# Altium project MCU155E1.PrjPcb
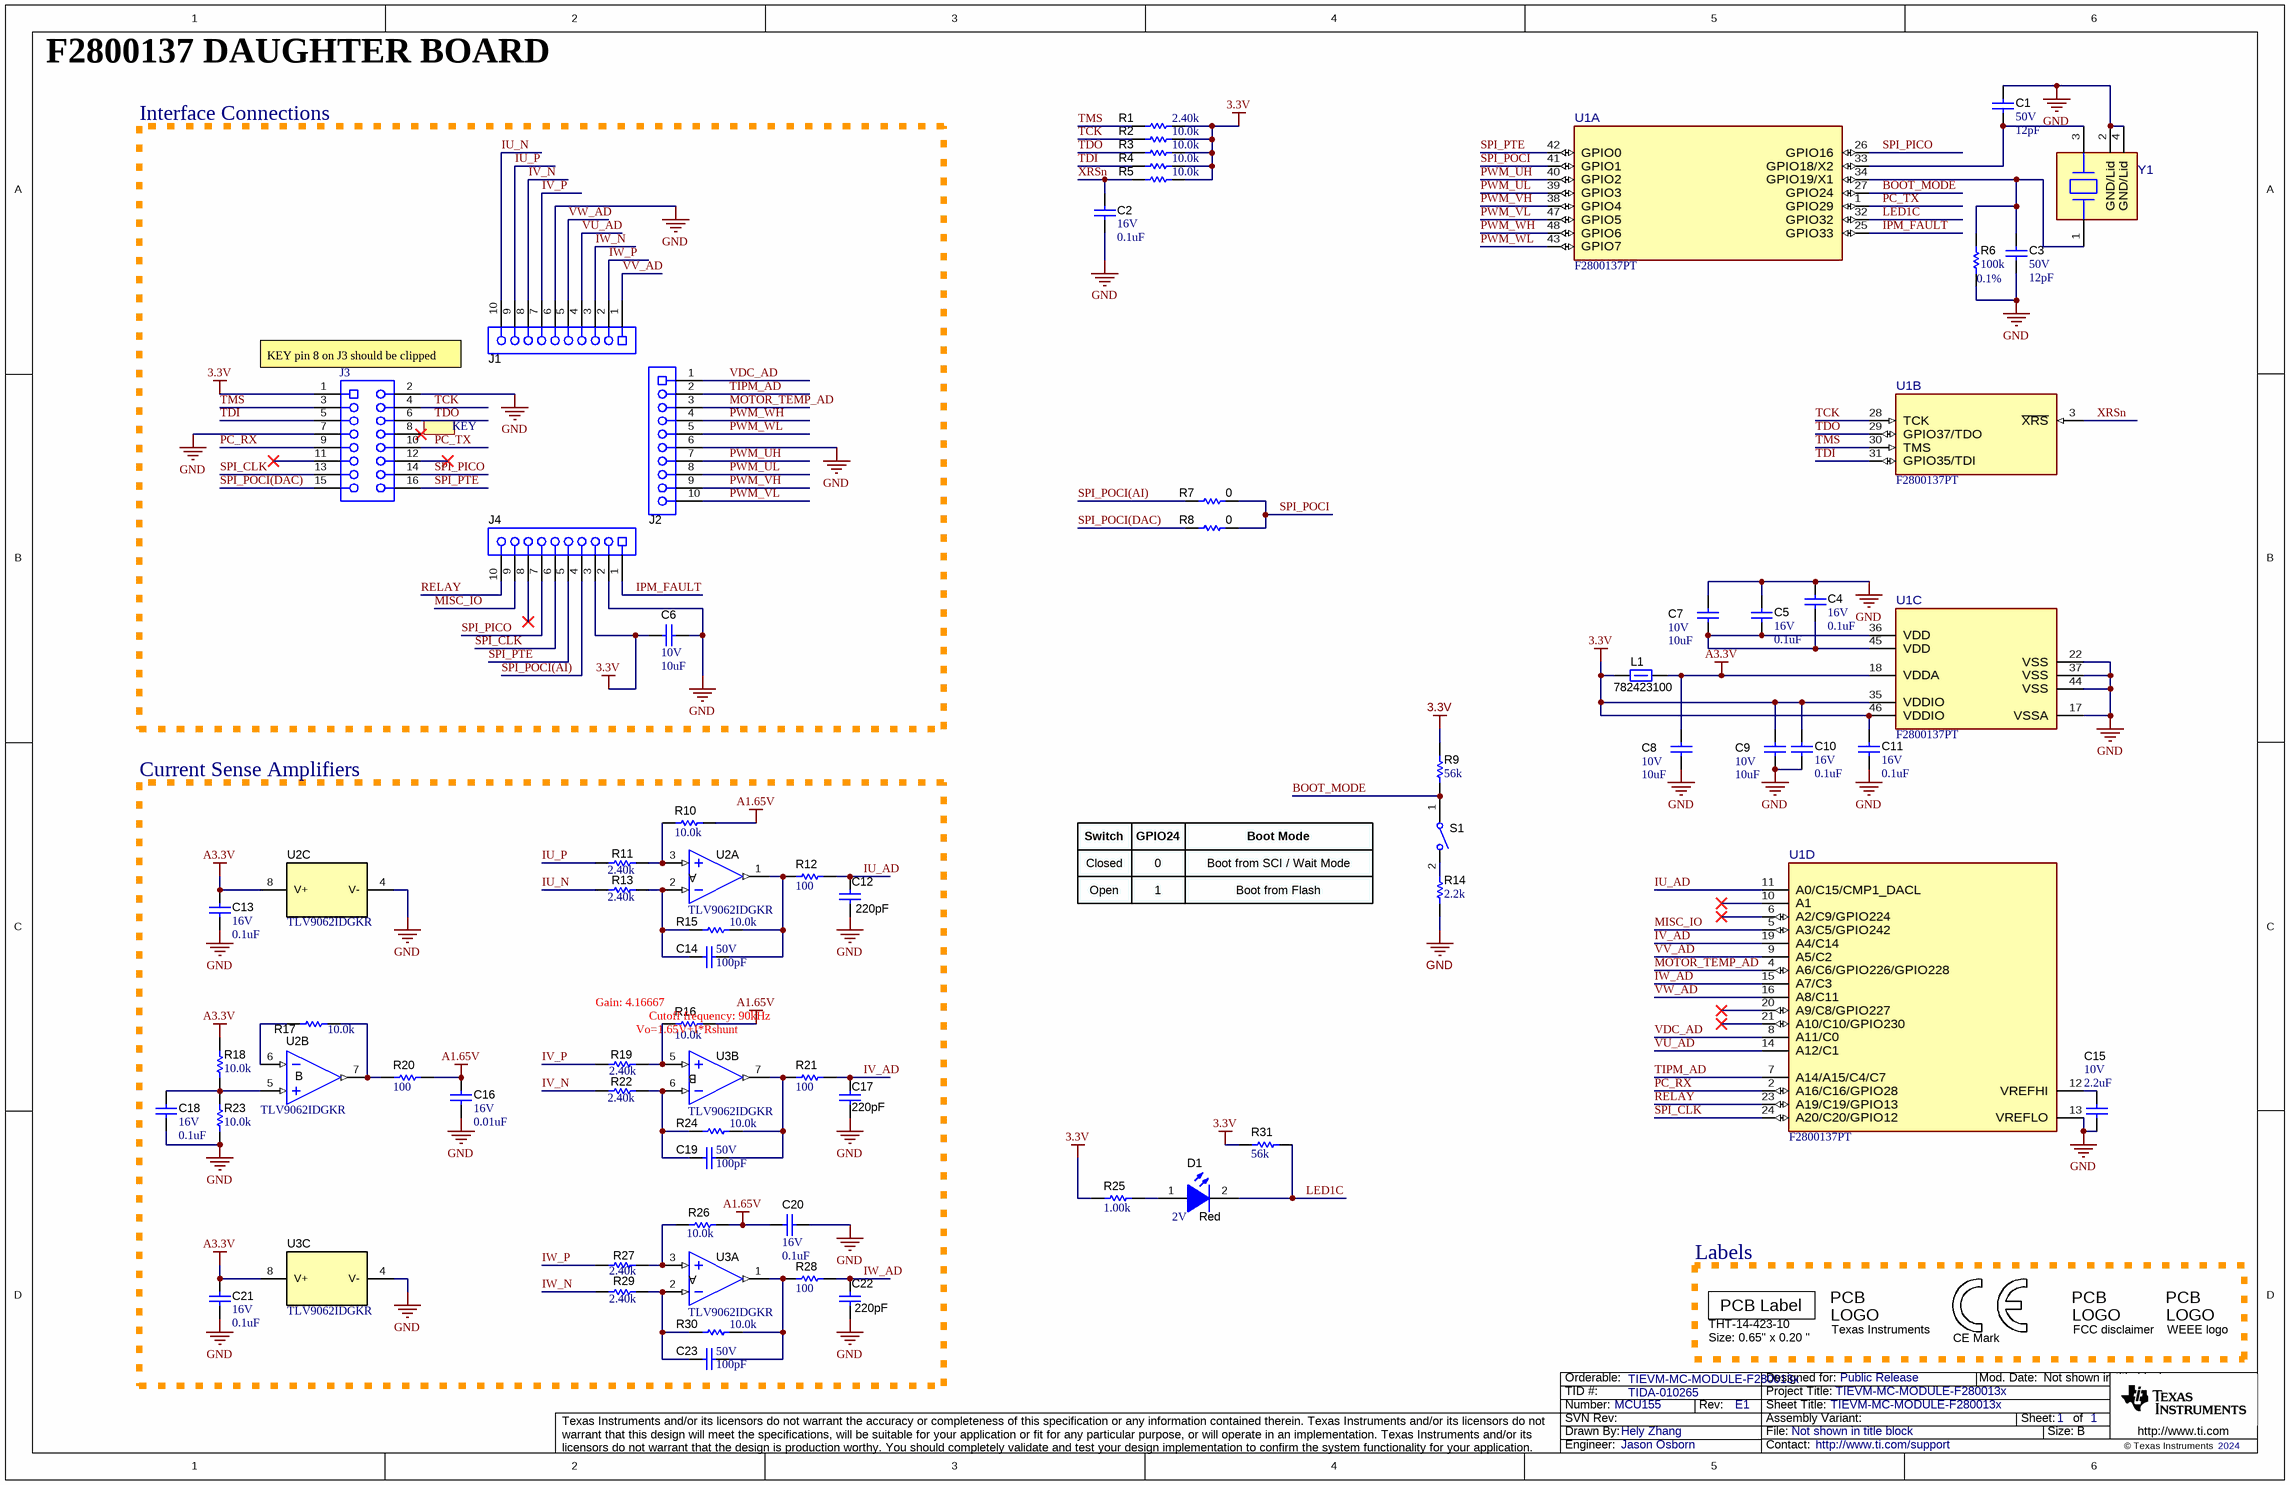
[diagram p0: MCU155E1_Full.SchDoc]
CopyrightYear: 2024; EVM_orderable: TIEVM-MC-MODULE-F280013x; PCB_Rev: E1; PRJ_Customer: Public Release; PRJ_Engineer: Jason Osborn; PRJ_Number: MCU155; PRJ_Title: TIEVM-MC-MODULE-F280013x; PRJ_Title_Short: TI-MC-M-F280013x; SCH_Rev: E1; TechSupport: http://www.ti.com/support; TID: TIDA-010265
1 sheet, 70 parts. Net scope: global (net labels, ports and power ports of the same name join across sheets).
Board file: MCU155E1_PCB.PcbDoc

## Sheet MCU155E1_Full.SchDoc: TIEVM-MC-MODULE-F280013x
size 431 x 279 mm; Date: Not shown in title block; ApprovedBy: Not shown in title block; CheckedBy: Not shown in title block; Author: Not shown in title block; CompanyName: Not shown in title block; DrawnBy: Hely Zhang; Engineer: Not shown in title block; Organization: Not shown in title block; Address1: Not shown in title block; Address2: Not shown in title block; Address3: Not shown in title block; Address4: Not shown in title block; DocumentNumber: 1; Revision: Use project parameter SCH_Rev; SheetNumber: 1; SheetTotal: 1; PageSetup: Record=PageOptions¦CenterHorizontal=True¦CenterVertical=True¦PrintScale=0.97¦XCorrection=1.00¦YCorrection=1.00¦PrintKind=0¦BorderSize=5000000¦LeftOffset=0¦BottomOffset=0¦Orientation=2¦PaperLength=1000¦PaperWidth=1000¦Scale=100¦PaperSource=15¦PrintQuality=600¦MediaType=1¦DitherType=10¦PaperKind=Letter¦PrintScaleMode=1

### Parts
C1  VDC_V: 50V  ValueDisplayed: 12pF  [0402]  (hidden comment: GRM1555C1H120JA01D)
C2  VDC_V: 16V  ValueDisplayed: 0.1uF  [0402]  (hidden comment: GRM155R71C104KA88D)
C3  VDC_V: 50V  ValueDisplayed: 12pF  [0402]  (hidden comment: GRM1555C1H120JA01D)
C4  VDC_V: 16V  ValueDisplayed: 0.1uF  [0402]  (hidden comment: GRM155R71C104KA88D)
C5  VDC_V: 16V  ValueDisplayed: 0.1uF  [0402]  (hidden comment: GRM155R71C104KA88D)
C6  VDC_V: 10V  ValueDisplayed: 10uF  [0402]  (hidden comment: GRM155R61A106ME11)
C7  VDC_V: 10V  ValueDisplayed: 10uF  [0402]  (hidden comment: GRM155R61A106ME11)
C8  VDC_V: 10V  ValueDisplayed: 10uF  [0402]  (hidden comment: GRM155R61A106ME11)
C9  VDC_V: 10V  ValueDisplayed: 10uF  [0402]  (hidden comment: GRM155R61A106ME11)
C10  VDC_V: 16V  ValueDisplayed: 0.1uF  [0402]  (hidden comment: GRM155R71C104KA88D)
C11  VDC_V: 16V  ValueDisplayed: 0.1uF  [0402]  (hidden comment: GRM155R71C104KA88D)
C12  Cap_F: 220pF  [0402]  (hidden comment: C1005C0G1H221F050BA)
C13  VDC_V: 16V  ValueDisplayed: 0.1uF  [0402]  (hidden comment: GRM155R71C104KA88D)
C14  VDC_V: 50V  ValueDisplayed: 100pF  [0402]  (hidden comment: GRM1555C1H101JA01D)
C15  VDC_V: 10V  ValueDisplayed: 2.2uF  [0402]  (hidden comment: GRM155R61A225ME95)
C16  VDC_V: 16V  ValueDisplayed: 0.01uF  [0402]  (hidden comment: GRM155R61C103KA01D)
C17  Cap_F: 220pF  [0402]  (hidden comment: C1005C0G1H221F050BA)
C18  VDC_V: 16V  ValueDisplayed: 0.1uF  [0402]  (hidden comment: GRM155R71C104KA88D)
C19  VDC_V: 50V  ValueDisplayed: 100pF  [0402]  (hidden comment: GRM1555C1H101JA01D)
C20  VDC_V: 16V  ValueDisplayed: 0.1uF  [0402]  (hidden comment: GRM155R71C104KA88D)
C21  VDC_V: 16V  ValueDisplayed: 0.1uF  [0402]  (hidden comment: GRM155R71C104KA88D)
C22  Cap_F: 220pF  [0402]  (hidden comment: C1005C0G1H221F050BA)
C23  VDC_V: 50V  ValueDisplayed: 100pF  [0402]  (hidden comment: GRM1555C1H101JA01D)
D1  value Red  Value2: 2V  [LTST-C193_Red]  (hidden comment: LTST-C193KRKT-5A)
J1  SSQ-110-03-T-S  [FP-SSQ-110-03-T-S_CONN_RCPT10-MFG]  (value not drawn)
J2  SSQ-110-03-T-S  [FP-SSQ-110-03-T-S_CONN_RCPT10-MFG]  (value not drawn)
J3  SSQ-108-03-T-D  [FP-SSQ-108-03-T-D_HDR16-MFG]  (value not drawn)
J4  SSQ-110-03-T-S  [FP-SSQ-110-03-T-S_CONN_RCPT10-MFG]  (value not drawn)
L1  782423100  [0402]
LBL1  THT-14-423-10  Note: Size: 0.65" x 0.20 "  [Label_650x200]
Logo1  CE Mark  [CE_Mark_5mm]  (no BOM)
Logo2  Texas Instruments  [TI_Symbol_Overlay_Small]  (no BOM)
Logo3  FCC disclaimer  [FCC_disclaimer_stacked]  (no BOM)
Logo4  WEEE logo  [WEEE_Minimum]  (no BOM)
R1  ValueDisplayed: 2.40k  [0402]  (hidden comment: ERJ-2RKF2401X)
R2  ValueDisplayed: 10.0k  [0402]  (hidden comment: RC0402FR-0710KL)
R3  ValueDisplayed: 10.0k  [0402]  (hidden comment: RC0402FR-0710KL)
R4  ValueDisplayed: 10.0k  [0402]  (hidden comment: RC0402FR-0710KL)
R5  ValueDisplayed: 10.0k  [0402]  (hidden comment: RC0402FR-0710KL)
R6  Value1: 0.1%  ValueDisplayed: 100k  [0402]  (hidden comment: RG1005P-104-B-T5)
R7  ValueDisplayed: 0  [0402]  (hidden comment: RC0402JR-070RL)
R8  ValueDisplayed: 0  [0402]  (hidden comment: RC0402JR-070RL)
R9  ValueDisplayed: 56k  [0402]  (hidden comment: CMP-0026949-3)
R10  ValueDisplayed: 10.0k  [0402]  (hidden comment: RC0402FR-0710KL)
R11  ValueDisplayed: 2.40k  [0402]  (hidden comment: ERJ-2RKF2401X)
R12  ValueDisplayed: 100  [0402]  (hidden comment: RC0402FR-07100RL)
R13  ValueDisplayed: 2.40k  [0402]  (hidden comment: ERJ-2RKF2401X)
R14  ValueDisplayed: 2.2k  [0402]  (hidden comment: CMP-0026890-5)
R15  ValueDisplayed: 10.0k  [0402]  (hidden comment: RC0402FR-0710KL)
R16  ValueDisplayed: 10.0k  [0402]  (hidden comment: RC0402FR-0710KL)
R17  ValueDisplayed: 10.0k  [0402]  (hidden comment: RC0402FR-0710KL)
R18  ValueDisplayed: 10.0k  [0402]  (hidden comment: RC0402FR-0710KL)
R19  ValueDisplayed: 2.40k  [0402]  (hidden comment: ERJ-2RKF2401X)
R20  ValueDisplayed: 100  [0402]  (hidden comment: RC0402FR-07100RL)
R21  ValueDisplayed: 100  [0402]  (hidden comment: RC0402FR-07100RL)
R22  ValueDisplayed: 2.40k  [0402]  (hidden comment: ERJ-2RKF2401X)
R23  ValueDisplayed: 10.0k  [0402]  (hidden comment: RC0402FR-0710KL)
R24  ValueDisplayed: 10.0k  [0402]  (hidden comment: RC0402FR-0710KL)
R25  ValueDisplayed: 1.00k  [0402]  (hidden comment: RC0402FR-071KL)
R26  ValueDisplayed: 10.0k  [0402]  (hidden comment: RC0402FR-0710KL)
R27  ValueDisplayed: 2.40k  [0402]  (hidden comment: ERJ-2RKF2401X)
R28  ValueDisplayed: 100  [0402]  (hidden comment: RC0402FR-07100RL)
R29  ValueDisplayed: 2.40k  [0402]  (hidden comment: ERJ-2RKF2401X)
R30  ValueDisplayed: 10.0k  [0402]  (hidden comment: RC0402FR-0710KL)
R31  ValueDisplayed: 56k  [0402]  (hidden comment: CMP-0026949-3)
S1  CHS-01TB  [SW_CHS-01TB]  (value not drawn)
U1  F2800137PT  [PT0048A-MFG]  (parts A,B,C,D of 4)
U2  TLV9062IDGKR  [DGK0008A_N]  (parts A,B,C of 3)
U3  TLV9062IDGKR  [DGK0008A_N]  (parts A,B,C of 3)
Y1  830108207209  [FP-830108207209_SMT_CRYSTAL_3MM2_2MM5-MFG]  (value not drawn)

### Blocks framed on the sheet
Interface Connections: C6 J1-J4
Current Sense Amplifiers: C12-C14 C16-C23 R10-R13 R15-R24 R26-R30 U2 U3
Labels: LBL1 Logo1-Logo4

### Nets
3.3V: C6.1 C9.1 C10.1 C11.1 J3.1 J4.3 L1.1 R1.2 R2.2 R3.2 R4.2 R5.2 R9.2 R25.1 R31.2 U1.35(VDDIO) U1.46(VDDIO)
A1.65V: C16.1 C20.1 R10.2 R16.2 R20.2 R26.2
A3.3V: C8.1 C13.1 C21.1 L1.2 R18.2 U1.18(VDDA) U2.8(V+) U3.8(V+)
GND: C1.1 C2.2 C3.2 C4.1 C5.1 C6.2 C7.1 C8.2 C9.2 C10.2 C11.2 C12.2 C13.2 C15.2 C16.2 C17.2 C18.2 C20.2 C21.2 C22.2 J1.6 J2.6 J3.2 J3.7 J4.2 R6.1 R14.2 R23.1 U1.13(VREFLO) U1.17(VSSA) U1.22(VSS) U1.37(VSS) U1.44(VSS) U2.4(V-) U3.4(V-) Y1.2(GND/Lid) Y1.4(GND/Lid)
BOOT_MODE: R9.1 S1.1 U1.27(GPIO24)
IPM_FAULT: J4.1 U1.25(GPIO33)
IU_AD: C12.1 R12.2 U1.11(A0/C15/CMP1_DACL)
IU_N: J1.10 R13.1
IU_P: J1.9 R11.1
IV_AD: C17.1 R21.2 U1.19(A4/C14)
IV_N: J1.8 R22.1
IV_P: J1.7 R19.1
IW_AD: C22.1 R28.2 U1.15(A7/C3)
IW_N: J1.3 R29.1
IW_P: J1.2 R27.1
LED1C: D1.2(K) R31.1 U1.32(GPIO32)
MISC_IO: J4.9 U1.5(A3/C5/GPIO242)
MOTOR_TEMP_AD: J2.3 U1.4(A6/C6/GPIO226/GPIO228)
PC_RX: J3.9 U1.2(A16/C16/GPIO28)
PC_TX: J3.10 U1.1(GPIO29)
PWM_UH: J2.7 U1.40(GPIO2)
PWM_UL: J2.8 U1.39(GPIO3)
PWM_VH: J2.9 U1.38(GPIO4)
PWM_VL: J2.10 U1.47(GPIO5)
PWM_WH: J2.4 U1.48(GPIO6)
PWM_WL: J2.5 U1.43(GPIO7)
RELAY: J4.10 U1.23(A19/C19/GPIO13)
SPI_CLK: J3.13 J4.6 U1.24(A20/C20/GPIO12)
SPI_PICO: J3.14 J4.7 U1.26(GPIO16)
SPI_POCI: R7.2 R8.2 U1.41(GPIO1)
SPI_POCI(AI): J4.4 R7.1
SPI_POCI(DAC): J3.15 R8.1
SPI_PTE: J3.16 J4.5 U1.42(GPIO0)
TCK: J3.4 R2.1 U1.28(TCK)
TDI: J3.5 R4.1 U1.31(GPIO35/TDI)
TDO: J3.6 R3.1 U1.29(GPIO37/TDO)
TIPM_AD: J2.2 U1.7(A14/A15/C4/C7)
TMS: J3.3 R1.1 U1.30(TMS)
VDC_AD: J2.1 U1.8(A11/C0)
VU_AD: J1.4 U1.14(A12/C1)
VV_AD: J1.1 U1.9(A5/C2)
VW_AD: J1.5 U1.16(A8/C11)
XRSn: C2.1 R5.1 U1.3(~{XRS})
NetC1_2: C1.2 U1.33(GPIO18/X2) Y1.3(2_Crystal)
NetC3_1: C3.1 R6.2 U1.34(GPIO19/X1) Y1.1(1_Crystal)
NetC4_2: C4.2 C5.2 C7.2 U1.36(VDD) U1.45(VDD)
NetC14_1: C14.1 R13.2 R15.1 U2.2(IN-)
NetC14_2: C14.2 R12.1 R15.2 U2.1(OUT)
NetC15_1: C15.1 U1.12(VREFHI)
NetC18_1: C18.1 R18.1 R23.2 U2.5(IN+)
NetC19_1: C19.1 R22.2 R24.1 U3.6(IN-)
NetC19_2: C19.2 R21.1 R24.2 U3.7(OUT)
NetC23_1: C23.1 R29.2 R30.1 U3.2(IN-)
NetC23_2: C23.2 R28.1 R30.2 U3.1(OUT)
NetD1_1: D1.1(A) R25.2
NetR10_1: R10.1 R11.2 U2.3(IN+)
NetR14_1: R14.1 S1.2
NetR16_1: R16.1 R19.2 U3.5(IN+)
NetR17_1: R17.1 R20.1 U2.7(OUT)
NetR17_2: R17.2 U2.6(IN-)
NetR26_1: R26.1 R27.2 U3.3(IN+)

Not connected (* = marked no-connect by the designer): J3 8* 11* 12*; J4 8*; U1 6(A2/C9/GPIO224)* 10(A1)* 20(A9/C8/GPIO227)* 21(A10/C10/GPIO230)*

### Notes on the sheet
- F2800137 DAUGHTER BOARD
- KEY pin 8 on J3 should be clipped
- (near J3) KEY
- Switch
- GPIO24
- Boot Mode
- Closed
- Open
- 0
- 1
- Boot from SCI / Wait Mode
- Boot from Flash
- Gain: 4.16667
- Vo=1.65V+I*Rshunt
- Cutoff frequency: 90kHz

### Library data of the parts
C1 C3 = CMP-0006415-2: CAP, CERM, 12 pF, 50 V, +/- 5%, C0G/NP0, 0402; Manufacturer: MuRata; TaMin_C: -55°C; Polarized: N; SizeAreaWB_mm2: 3; Value1: Unknown; U/M: EA; Value: 12pF; TaMax_C: 125°C; SizeZ_mm: 0.6; SizeX_mm: 1; SizeY_mm: 0.5; AEC Category: Q200
C2 C4 C5 C10 C11 C13 C18 C20 C21 = CMP-0006641-2: CAP, CERM, 0.1 uF, 16 V, +/- 10%, X7R, 0402; Manufacturer: MuRata; TaMin_C: -55°C; Polarized: N; SizeAreaWB_mm2: 3; Value1: Unknown; U/M: EA; Value: 0.1uF; TaMax_C: 125°C; SizeZ_mm: 0.6; SizeX_mm: 1; SizeY_mm: 0.5; Cap_F: 100nF; AEC Category: Q200
C6-C9 = CMP-0006564-1: CAP, CERM, 10 uF, 10 V, +/- 20%, X5R, 0402; Manufacturer: MuRata; TaMin_C: -55°C; Polarized: N; SizeAreaWB_mm2: 3; Value1: Unknown; U/M: EA; Value: 10uF; TaMax_C: 85°C; SizeZ_mm: 0.6; SizeX_mm: 1; SizeY_mm: 0.5; Cap_F: 10µF; AEC Category: Q200
C12 C17 C22 = CMP-0006249-2: CAP, CERM, 220 pF, 50 V, +/- 1%, C0G/NP0, 0402; Manufacturer: TDK; TaMin_C: -55°C; Polarized: N; SizeAreaWB_mm2: 3; Value1: Unknown; U/M: EA; Value: 220pF; TaMax_C: 125°C; SizeZ_mm: 0.6; SizeX_mm: 1; SizeY_mm: 0.5; Value2: 50V; AEC Category: Q200
C14 C19 C23 = CMP-0006410-2: CAP, CERM, 100 pF, 50 V, +/- 5%, C0G/NP0, 0402; Manufacturer: MuRata; TaMin_C: -55°C; Polarized: N; SizeAreaWB_mm2: 3; Value1: Unknown; U/M: EA; Value: 100pF; TaMax_C: 125°C; SizeZ_mm: 0.6; SizeX_mm: 1; SizeY_mm: 0.5; AEC Category: Q200
C15 = CMP-0006571-2: CAP, CERM, 2.2 uF, 10 V, +/- 20%, X5R, 0402; Manufacturer: MuRata; TaMin_C: -55°C; Polarized: N; SizeAreaWB_mm2: 3; Value1: Unknown; U/M: EA; Value: 2.2uF; TaMax_C: 85°C; SizeZ_mm: 0.6; SizeX_mm: 1; SizeY_mm: 0.5; Cap_F: 2.2µF; AEC Category: Q200
C16 = CMP-0006590-2: CAP, CERM, 0.01 uF, 16 V, +/- 10%, X5R, 0402; Manufacturer: MuRata; TaMin_C: -55°C; Polarized: N; SizeAreaWB_mm2: 3; Value1: Unknown; U/M: EA; Value: 0.01uF; TaMax_C: 85°C; SizeZ_mm: 0.6; SizeX_mm: 1; SizeY_mm: 0.5; Cap_F: 10nF; AEC Category: Q200
D1 = CMP-0079922-3: LED, Red, SMD; Manufacturer: Lite-On; SizeX_mm: 1.6; SizeY_mm: 0.8; Green_REACh: Incomplete; SizeAreaWB_mm2: 4.68; Green_Lifecycle: Not Set; Value1: W; Io_A: 5mA; Type: AlInGaP; SizeZ_mm: 0.45; Tjmax_C: 85°C; SizeArea_mm2: 1.28
J1 J2 J4 = CMP-0123041-2: Conn Socket Strip SKT 10 POS 2.54mm Solder ST Top Entry Thru-Hole Bulk; Manufacturer: Samtec; ContactFinish: Tin,Nickel; Current_A: 6.3A; Row_Count: 1; Voltage_V: 655V; AEC Qualified: No; Category 0836C53C3D42D3F1: Connectors; Category 75Fab8F04590Ae3D: Connectors and Adapters; Category A0826D8895867B45: Rectangular Industrial Connectors; Category Bda670Ac885E6661: Uncategorized; Category E7012A0Bd22E3Cc6: Headers & Receptacles; Conn Gender: Female; Conn Orientation: Vertical; Is Female: yes; SizeZ_mm: 8.64mm
J3 = CMP-0123022-2: 16 Position Receptacle Connector 0.100" (2.54mm) Through Hole Tin; Manufacturer: Samtec; ContactFinish: Tin,Nickel; Current_A: 6.3A; Row_Count: 2; Voltage_V: 655V; AEC Qualified: No; Category 0836C53C3D42D3F1: Connectors; Category 75Fab8F04590Ae3D: Connectors and Adapters; Category A0826D8895867B45: Rectangular Industrial Connectors; Category Bda670Ac885E6661: Uncategorized; Category E7012A0Bd22E3Cc6: Headers & Receptacles; Conn Gender: Female; Conn Orientation: Vertical; Is Female: yes; SizeZ_mm: 8.64mm
L1 = CMP-0003274-1: Ferrite Bead, 10 ohm @ 100 MHz, 1.5 A, 0402; Manufacturer: Wurth Elektronik; Ztyp@1GHz_Ohm: 15.135; ZTyp@100MHz_Ohm: 10; SizeAreaWB_mm2: 3; DCR_ohm: 0.03; Value1: 0.03 ohm; Value: 10 ohm; Imax_A: 1.5A; SizeZ_mm: 0.6; SizeX_mm: 1; SizeY_mm: 0.5
LBL1 = CMP-0003625-1: Thermal Transfer Printable Labels, 0.650" W x 0.200" H - 10,000 per roll; Manufacturer: Brady; CompType: Label
Logo1 = CMP-0074844-1: SymbolCreator: a0412235
Logo2 = CMP-0074838-1: Texas Instrument Corporate Signature; SymbolCreator: a0412235; Lib Reference: TI_Logo; Library Reference: Logo
Logo3 = CMP-0074847-1: FCC_disclaimer; Library Reference: Logo
Logo4 = CMP-0074769-1
R1 R11 R13 R19 R22 R27 R29 = CMP-0026685-1: RES, 2.40 k, 1%, 0.1 W, AEC-Q200 Grade 0, 0402; Manufacturer: Panasonic; Power_W: 100mW; TempCo: 100 ppm/C; Value_Code: 2k40; U/M: EA; Value: 2.40k; Res_ohm: 2.4k; SizeX_mm: 1; SizeY_mm: 0.5; SizeZ_mm: 0.6; Value2: 0.1W; AEC Qualified: Y; AEC Grade: 0; AEC Category: Q200
R2-R5 R10 R15-R18 R23 R24 R26 R30 = CMP-0078669-1: RES, 10.0 k, 1%, 0.063 W, 0402; Manufacturer: Yageo America; Power_W: 63mW; Green_Lifecycle: Active; TempCo: 100 ppm/C; Value_Code: 10k0; Green_REACh: Passed; Value: 10.0k; EIA_Code: E96; Res_ohm: 10k; SizeX_mm: 1; SizeY_mm: 0.5; SizeZ_mm: 0.6; Value2: 0.063W; AEC Qualified: N; AEC Category: Q200
R6 = CMP-0026815-1: RES, 100 k, 0.1%, 0.063 W, 0402; Manufacturer: Susumu Co Ltd; Power_W: 63mW; TempCo: 25 ppm/C; U/M: EA; Value: 100k; EIA_Code: E192; SizeX_mm: 1; SizeY_mm: 0.5; SizeZ_mm: 0.6; Value2: 0.063W; AEC Category: Q200
R7 R8 = CMP-0027004-2: RES, 0, 5%, 0.063 W, 0402; Manufacturer: Yageo America; Power_W: 63mW; TempCo: 200 ppm/C; Value_Code: 0000; U/M: EA; Value: 0; EIA_Code: E24; SizeX_mm: 1; SizeY_mm: 0.5; SizeZ_mm: 0.6; Value2: 0.063W; VDC_V: 50V; AEC Category: Q200
R9 R31 = CMP-0026949-3: RES, 56 k, 5%, 0.063 W, AEC-Q200 Grade 0, 0402; PartNumber: CRCW040256K0JNED; Manufacturer: Vishay-Dale; Value: 56k; Value_Code: 56k0; Power_W: 63mW; Value2: 0.063W; VDC_V: 50V; TempCo: 200 ppm/C; EIA_Code: E24; AEC Category: Q200; AEC Qualified: Y; AEC Grade: 0; SizeArea_mm2: 0.5; SizeX_mm: 1; SizeZ_mm: 0.6
R12 R20 R21 R28 = CMP-0026722-1: RES, 100, 1%, 0.063 W, 0402; Manufacturer: Yageo America; Power_W: 63mW; TempCo: 100 ppm/C; Value_Code: 100R; U/M: EA; Value: 100; EIA_Code: E96; SizeX_mm: 1; SizeY_mm: 0.5; SizeZ_mm: 0.6; Value2: 0.063W; AEC Qualified: N; VDC_V: 50V; AEC Category: Q200
R14 = CMP-0026890-5: RES, 2.2 k, 5%, 0.063 W, AEC-Q200 Grade 0, 0402; PartNumber: CRCW04022K20JNED; Manufacturer: Vishay-Dale; Value: 2.2k; Value_Code: 2k20; Power_W: 63mW; Value2: 0.063W; VDC_V: 50V; TempCo: 200 ppm/C; EIA_Code: E24; AEC Category: Q200; AEC Qualified: Y; AEC Grade: 0; SizeArea_mm2: 0.5; SizeX_mm: 1; SizeZ_mm: 0.6
R25 = CMP-0026725-1: RES, 1.00 k, 1%, 0.0625 W, 0402; Manufacturer: Yageo America; Power_W: 62.5mW; TempCo: 100 ppm/C; Value_Code: 1k00; U/M: EA; Value: 1.00k; EIA_Code: E96; Res_ohm: 1k; SizeX_mm: 1; SizeY_mm: 0.5; SizeZ_mm: 0.6; AEC Qualified: N; VDC_V: 50V; AEC Category: Q200
S1 = CMP-0002163-2: Switch, Slide, SPST, Top Slide, SMT; Manufacturer: Copal Electronics; CurrentRating_mA: 100A; SwitchFunction: Off-On; VDC_V: 6V; PositionCount: 1
U1 = CMP-0096487-1: Real-Time Microcontrollers; Manufacturer: Texas Instruments; Number Of Pwm Channels: 14; Number Of Spi Channels: 1; Memory Type: FLASH; Frequency_Fixed: 120MHz; TaMin_C: -40°C; Number Of I2C Channels: 2; AEC Qualified: No; TaMax_C: +125°C; Number Of Adc Channels: 17; Ram Size: 36KBytes; Min Supply Voltage: 2.8V; Number Of Timers/Counters: 4; Core Architecture: TMS320C28x; Data Bus Width: 32bits; Number Of Uart Channels: 3; SizeZ_mm: 1.6mm; Memory Size: 256KBytes; Standoff Height: 0.5mm; Max Supply Voltage: 3.63V; Number Of I/Os: 25; Interface: I2C,SPI,UART,CAN,SCI,SMBus
U2 U3 = CMP-0084063-1: 10-MHz, Low-Noise, RRIO, CMOS Operational Amplifier for Cost-Sensitive Systems, DGK0008A (VSSOP-8); Manufacturer: Texas Instruments; Alternate PartNumber: TLV9062IDGKT; Rating: Catalog; SizeAreaWB_mm2: 23.6; SizeArea_mm2: 14.7; AEC Qualified: N; AEC Category: Q200; SizeZ_mm: 1.1; SizeY_mm: 3; CompType: IC; SizeX_mm: 4.9
Y1 = CMP-0093781-1: 20 MHz ±10ppm Crystal 8pF 50 Ohms 4-SMD, No Lead; Manufacturer: Wurth Electronics; SizeZ_mm: 0.8mm; Frequency Stability: 20ppm; Esr: 50; Frequency_Fixed: 20MHz

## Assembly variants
001: not fitted R6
